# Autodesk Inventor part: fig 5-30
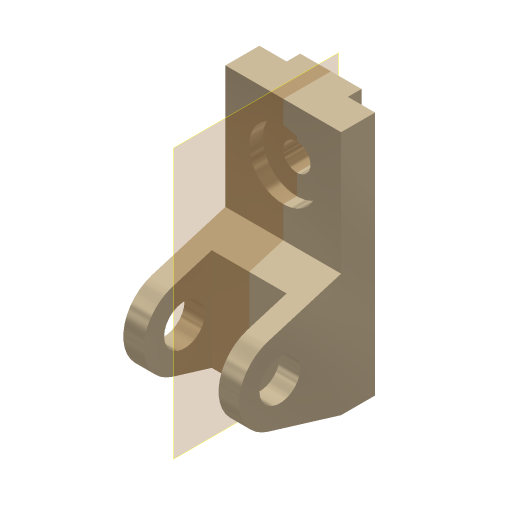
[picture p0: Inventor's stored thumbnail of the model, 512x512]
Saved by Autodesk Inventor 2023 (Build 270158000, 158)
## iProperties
Created: 2001-11
Part Number: fig 5-30
Document SubType Name: Modeling
Designer: Renu Muthoo
Density: 1 g/cm^3
Material: Generic
Appearance: Metal-Titanium (Polished)
Control State: 0
Master: False
Checked Out: False
Shininess: 65.0
Angle Display Precision: 2
Document Length Units: 11269
Document Angle Units: 11279
Document Time Units: 11290
Document Mass Units: 11283
Document Length Units Precision: 3
Document Angle Units Precision: 2
Density: 0.0
Volumn: 0.0
Area: 0.0
PropertySet Name: Model Information
Author: Renu Muthoo
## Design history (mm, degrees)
node "Sketch1"
sketch "Sketch2"
  geometry: L1 (33.257, 104.664)-(33.257, -75.336); L2 (33.257, -75.336)-(8.257, -75.336); L3 (8.257, -75.336)-(-45.451, -59.045); L4 (-45.451, -1.628)-(8.257, 14.664); L5 (8.257, 14.664)-(8.257, 104.664); L6 (8.257, 104.664)-(33.257, 104.664); C1 r 15 at (-36.743, -30.336); A1 r 30 centre (-36.743, -30.336) between (-45.451, -1.628) and (-45.451, -59.045)
  constraints: 12 end point, 2 centre point, 2 equal length, 2 parallel, 2 point on circle, 2 tangent, 1 coincident, 1 perpendicular, 1 vertical
  dimensions: "d0" = 180 distance of L1.start L1.end; "d1" = 30 radius of A1; "d2" = 25 distance of L5.end L1.start; "d3" = 45 distance from line of L2 A1.centre; "d4" = 70 distance from line of L1 A1.centre; "d5" = 30 diameter of C1
extrude "Extrusion1" new body sketch "Sketch2" distance "d6" = 85; taper "d7" = 0 deg
workplane "Work Plane1"
sketch "Sketch3"
  geometry: L1 (15, 62.364)-(70, 62.364); L2 (70, 62.364)-(70, -52.386); L3 (70, -52.386)-(15, -52.386); L4 (15, -52.386)-(15, 62.364); L5 (0, -45)-(0, -28.708) reference
  constraints: 8 end point, 2 parallel, 1 horizontal, 1 perpendicular
  dimensions: "d8" = 55 distance of L1.start L1.end; "d9" = 15 distance between parallel lines of L5 L4
extrude "Extrusion2" cut sketch "Sketch3" distance "d10" = 50; taper "d11" = 0 deg
sketch "Sketch4"
  geometry: L1 (0, 25)-(85, 25) reference; L2 (0, 0)-(0, 25) reference; L3 (20, 25)-(65, 25); L4 (65, 25)-(65, 35); L5 (65, 35)-(20, 35); L6 (20, 35)-(20, 25)
  constraints: 8 end point, 2 parallel, 1 horizontal, 1 perpendicular, 1 point on line
  dimensions: "d12" = 45 distance of L4.end L5.end; "d13" = 10 distance of L3.end L4.end; "d14" = 20 distance between parallel lines of L2 L6
extrude "Extrusion3" join sketch "Sketch4" stored distance "d15" = 50; taper "d16" = 0 deg
sketch "Sketch5"
  geometry: L1 (85, 0)-(85, 90) reference; L2 (0, 90)-(85, 90) reference; 1 further point
  dimensions: "d17" = 42 distance from line of L2 point (42.5, 48); "d18" = 42.5 distance from line of L1 point (42.5, 48)
hole "Hole1" sketch "Sketch5" at (42.5, 48) diameter "d19" = 20; stored, may be unused: countersink angle "d23" = 82 deg, drill point angle "d25" = 118 deg; dims "d20" = 6, "d21" = 50, "d22" = 10, "d24" = 8
workplane "Work Plane5"
body "Solid1"
